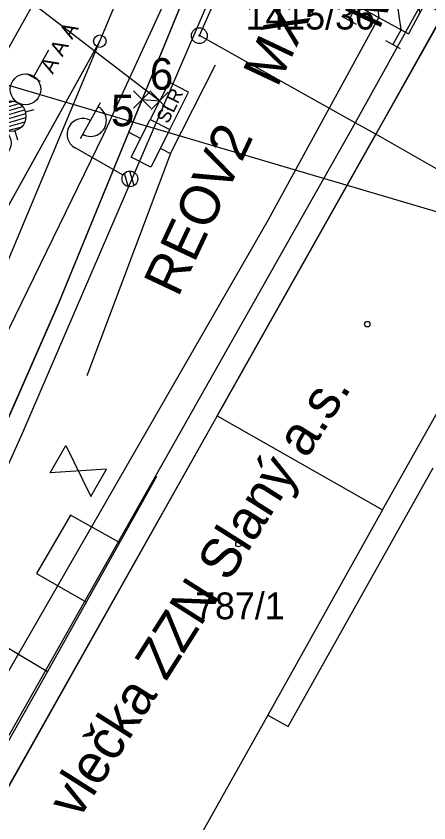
# Model space of a CAD drawing. Extents: x -781083 to -763634, y -1029516 to -1022695.
# Drawn here: x -764960.5 to -764934.3, y -1023880.9 to -1023829.7 of the extents above; entities that cross this region are included whole.
import ezdxf

# ---------------------------------------------------------------- set-up
doc = ezdxf.new("R2010")
doc.units = 0
for name, color, linetype in [('Default', 7, 'Continuous'), ('Hranice parcel', 7, 'Continuous'), ('Parcelní čísla', 7, 'Continuous'), ('PS110211-body_krizky', 7, 'Continuous'), ('PS110211-body_text', 7, 'Continuous'), ('PS120111-MOK', 7, 'Continuous'), ('PS_12-01-10_Kabelizace_nove_kabelizace', 7, 'Continuous'), ('PS_12-01-11_SZZ_Slany_nove_prvky', 7, 'Continuous'), ('PS_12-01-11_SZZ_Slany_rusene_prvky', 7, 'Continuous'), ('SO128401_EOV_popisky', 7, 'Continuous'), ('SO128401_EOV_prvky', 7, 'Continuous'), ('SO128401_EOV_trasa', 7, 'Continuous'), ('SO128602_NN_trasa', 7, 'Continuous'), ('Vnitřní kresba', 7, 'Continuous'), ('Vodafone_ vzduch', 7, 'Continuous'), ('Vrstva 1', 7, 'Continuous'), ('Vrstva 15', 7, 'Continuous'), ('Vrstva 17', 7, 'Continuous'), ('Vrstva 2', 7, 'Continuous'), ('Vrstva 21', 7, 'Continuous'), ('Vrstva 23', 7, 'Continuous'), ('Vrstva 25', 7, 'Continuous'), ('Vrstva 33', 7, 'Continuous'), ('Značky bodu BP', 7, 'Continuous'), ('Značky budov', 7, 'Continuous'), ('ČD Telematika_TK', 7, 'Continuous')]:
    doc.layers.add(name, color=color, linetype=linetype)

# ---------------------------------------------------------------- blocks, each defined once
blk = doc.blocks.new('4.02')
at = {"layer": 'Značky budov'}
blk.add_circle((-0.07, 0.01), 1.75, dxfattribs=at)
blk = doc.blocks.new('1.05')
at = {"layer": 'Značky bodu BP'}
for radius in [5, 0.303]:
    blk.add_circle((0, 0), radius, dxfattribs=at)
blk = doc.blocks.new('POINT_DISPLAY')
at = {"layer": 'Default'}
blk.add_line((0, 0), (0, 0), dxfattribs=at)
blk = doc.blocks.new('C689')
at = {"layer": 'Vrstva 15'}
for p, q in [((-10.66, 21.33), (-10.66, 10.66)), ((0, 21.33), (21.33, 21.34)), ((0, 16), (6.4, 21.33)), ((0, 21.33), (0, -21.33)), ((21.33, 21.34), (21.34, -21.33)), ((-10.66, 16), (0, 16)), ((21.33, 16), (0, 0)), ((0, -16), (21.33, 0)), ((-10.66, -10.66), (-10.66, -21.33)), ((0, -16), (-10.66, -16)), ((21.33, -16), (14.93, -21.33)), ((21.34, -21.33), (0, -21.33))]:
    blk.add_line(p, q, dxfattribs=at)
blk.add_blockref('POINT_DISPLAY', (0, 16), dxfattribs=at)
blk = doc.blocks.new('C687')
at = {"layer": 'Vrstva 21'}
blk.add_lwpolyline([(-10, -15), (10, -15), (-10, 15), (10, 15), (-10, -15)], dxfattribs=at)
blk = doc.blocks.new('C669_2')
at = {"layer": 'Vrstva 25'}
for p, q in [((0, 5), (0, 40)), ((6.99, 40), (33, 40)), ((-4.78, -1.46), (1.44, 4.76)), ((-2.39, -4.37), (4.38, 2.4))]:
    blk.add_line(p, q, dxfattribs=at)
blk.add_circle((0, 0), 5, dxfattribs=at)
blk.add_circle((0, 0), 5, dxfattribs=at)
for centre, start, end in [((10, 40), 359.9999, 179.9999), ((20, 39.88), 179.2973, 0.7025)]:
    blk.add_arc(centre, 10, start, end, dxfattribs=at)
blk = doc.blocks.new('C083_1')
at = {"layer": 'Vrstva 2'}
blk.add_circle((0, 0), 4, dxfattribs=at)
blk = doc.blocks.new('NS8')
at = {"layer": 'PS_12-01-11_SZZ_Slany_nove_prvky'}
for p, q in [((-10.61, 85.61), (-17, 92)), ((-14.92, 73.72), (1.27, 89.91)), ((-14.24, 79.71), (-4.75, 89.19)), ((-13.91, 69.42), (5.56, 88.89)), ((-11.99, 66.04), (8.96, 86.99)), ((10.61, 85.61), (17, 92)), ((-9.38, 63.35), (11.66, 84.39)), ((-6.1, 61.33), (13.69, 81.12)), ((-1.96, 60.16), (14.86, 76.98)), ((3.63, 60.45), (14.51, 71.33)), ((-10.61, 64.39), (-17, 58)), ((10.61, 64.39), (17, 58)), ((0, 30), (0, 0)), ((-15, 0), (15, 0))]:
    blk.add_line(p, q, dxfattribs=at)
for centre, radius in [((0, 105), 15), ((0, 75), 15), ((0, 45), 15), ((0, 45), 7)]:
    blk.add_circle(centre, radius, dxfattribs=at)
blk = doc.blocks.new('C016_3')
at = {"layer": 'PS_12-01-11_SZZ_Slany_rusene_prvky'}
for p, q in [((0, 5), (0, -5)), ((19.8, 0), (0, 0))]:
    blk.add_line(p, q, dxfattribs=at)

msp = doc.modelspace()

# ---------------------------------------------------------------- linework, layer by layer
at = {"layer": 'Hranice parcel'}
for points in [[(-764938.97, -1023836.45), (-764948.87, -1023830.92), (-764940.22, -1023811.42)], [(-764925.35, -1023824.17), (-764928.73, -1023830.14), (-764932.49, -1023827.93), (-764933.39, -1023829.54), (-764934.71, -1023828.79), (-764938.97, -1023836.45)], [(-764938.97, -1023836.45), (-764967.04, -1023886), (-764962.72, -1023888.96), (-764967.7, -1023897.5)], [(-764927.18, -1023843.13), (-764930.69, -1023841.15), (-764937.66, -1023837.18), (-764938.97, -1023836.45)]]:
    msp.add_lwpolyline(points, dxfattribs=at)
at = {"layer": 'PS110211-body_krizky'}
for p, q in [((-764953.054, -1023835.526), (-764951.954, -1023834.426)), ((-764951.954, -1023835.526), (-764953.054, -1023834.426)), ((-764953.054, -1023835.526), (-764951.954, -1023834.426)), ((-764951.954, -1023835.526), (-764953.054, -1023834.426)), ((-764951.943, -1023835.61), (-764950.843, -1023834.51)), ((-764950.843, -1023835.61), (-764951.943, -1023834.51)), ((-764951.943, -1023835.61), (-764950.843, -1023834.51)), ((-764950.843, -1023835.61), (-764951.943, -1023834.51)), ((-764952.504, -1023834.976), (-764952.504, -1023834.976)), ((-764952.504, -1023834.976), (-764952.504, -1023834.976)), ((-764951.393, -1023835.06), (-764951.393, -1023835.06)), ((-764951.393, -1023835.06), (-764951.393, -1023835.06))]:
    msp.add_line(p, q, dxfattribs=at)
at = {"layer": 'PS120111-MOK'}
msp.add_lwpolyline([(-764950.795, -1023833.874), (-764951.991, -1023836.246), (-764950.754, -1023836.87), (-764949.558, -1023834.498)], close=True, dxfattribs=at)
msp.add_lwpolyline([(-765225.805, -1024328.474), (-765227.041, -1024327.403), (-765189.607, -1024263.284), (-765167.089, -1024223.521), (-765111.836, -1024124.939), (-765108.851, -1024119.501), (-765085.73, -1024077.899), (-765081.023, -1024080.523), (-765060.822, -1024044.042), (-765057.835, -1024038.647), (-765021.888, -1023965.037), (-765009.529, -1023945.01), (-764990.029, -1023909.994), (-764973.93, -1023884.565), (-764957.796, -1023847.878), (-764953.349, -1023837.037), (-764952.504, -1023834.976), (-764951.393, -1023835.06)], dxfattribs=at)
at = {"layer": 'PS_12-01-10_Kabelizace_nove_kabelizace'}
msp.add_line((-764957.796, -1023847.878), (-764973.93, -1023884.565), dxfattribs=at)
msp.add_lwpolyline([(-764926.5, -1023779.725), (-764935.477, -1023793.468), (-764957.811, -1023847.911)], dxfattribs=at)
at = {"layer": 'SO128401_EOV_prvky'}
msp.add_lwpolyline([(-764950.754, -1023836.87), (-764951.962, -1023839.265), (-764953.199, -1023838.642), (-764951.991, -1023836.246)], close=True, dxfattribs=at)
at = {"layer": 'SO128401_EOV_trasa'}
for points in [[(-764953.349, -1023837.037), (-764935.477, -1023793.468), (-764926.5, -1023779.725), (-764918.394, -1023762.933), (-764916.418, -1023759.423), (-764914.161, -1023755.412), (-764908.579, -1023744.414)], [(-765060.824, -1024044.045), (-765057.835, -1024038.647), (-765021.888, -1023965.037), (-765009.529, -1023945.01), (-764990.029, -1023909.994), (-764973.93, -1023884.565), (-764973.93, -1023884.565), (-764957.796, -1023847.878), (-764957.796, -1023847.878), (-764953.349, -1023837.037), (-764953.349, -1023837.037), (-764952.595, -1023837.444), (-764952.595, -1023837.444), (-764952.595, -1023837.444), (-764952.595, -1023837.444)]]:
    msp.add_lwpolyline(points, dxfattribs=at)
at = {"layer": 'SO128602_NN_trasa'}
for points in [[(-764951.358, -1023838.068), (-764950.698, -1023838.4), (-764947.844, -1023832.776)], [(-764950.698, -1023838.4), (-764956.028, -1023852.51)]]:
    msp.add_lwpolyline(points, dxfattribs=at)
at = {"layer": 'Vnitřní kresba'}
for p, q in [((-764933.39, -1023829.54), (-764937.66, -1023837.18)), ((-764947.74, -1023855.04), (-764937.66, -1023837.18)), ((-764937.24, -1023861.02), (-764931.63, -1023851.06)), ((-764947.74, -1023855.04), (-764963.43, -1023882.91)), ((-764947.74, -1023855.04), (-764937.24, -1023861.02)), ((-764943.23, -1023874.77), (-764934.01, -1023858.35)), ((-764937.24, -1023861.02), (-764944.52, -1023874.04)), ((-764944.52, -1023874.04), (-764949.74, -1023883.33)), ((-764944.52, -1023874.04), (-764943.23, -1023874.77))]:
    msp.add_line(p, q, dxfattribs=at)
at = {"layer": 'Vodafone_ vzduch'}
msp.add_line((-764902.64, -1023851.29), (-765047.77, -1023808.471), dxfattribs=at)
at = {"layer": 'Vrstva 1'}
for points in [[(-765057.199, -1024002.967), (-765051.483, -1023992.806), (-765043.706, -1023978.953), (-765034.751, -1023962.958), (-765025.899, -1023947.163), (-765016.568, -1023930.575), (-765007.818, -1023915.05), (-764998.815, -1023899.045), (-764993.349, -1023889.308), (-764987.511, -1023878.918), (-764981.006, -1023867.343), (-764973.154, -1023853.353), (-764966.496, -1023841.495), (-764959.274, -1023828.66), (-764951.948, -1023815.612), (-764946.772, -1023806.407), (-764938.618, -1023791.934), (-764931.244, -1023778.835), (-764930.485, -1023777.473), (-764927.033, -1023771.438), (-764925.317, -1023768.417), (-764917.098, -1023753.973)], [(-765021.966, -1023959.899), (-765020.98, -1023958.139), (-765020.338, -1023956.998), (-765016.5, -1023950.137), (-765007.832, -1023934.643), (-765003.16, -1023926.347), (-764995.027, -1023911.884), (-764988.083, -1023899.535), (-764983.024, -1023890.503), (-764978.046, -1023881.533), (-764973.443, -1023872.721), (-764971.379, -1023868.593), (-764967.7, -1023860.663), (-764964.253, -1023852.828), (-764961.628, -1023846.609), (-764955.193, -1023831.268), (-764949.378, -1023817.406), (-764948.769, -1023815.942), (-764946.974, -1023811.649), (-764945.113, -1023807.171), (-764938.618, -1023791.934)], [(-764992.669, -1023917.221), (-764979.299, -1023898.88), (-764973.72, -1023891.071), (-764965.108, -1023878.355), (-764944.509, -1023842.632), (-764937.461, -1023829.77)], [(-765052.709, -1024004.781), (-765046.025, -1023992.89), (-765034.924, -1023973.118), (-765026.269, -1023957.734), (-765017.76, -1023942.588), (-765010.012, -1023928.764), (-765001.938, -1023914.334), (-764994.407, -1023900.905), (-764986.605, -1023887.067), (-764981.397, -1023877.846), (-764975.574, -1023867.554), (-764972.605, -1023862.288), (-764968.241, -1023854.565), (-764963.27, -1023845.769), (-764955.193, -1023831.268)]]:
    msp.add_lwpolyline(points, dxfattribs=at)
at = {"layer": 'Vrstva 17'}
for points in [[(-764965.992, -1023885.405), (-764965.453, -1023883.54), (-764958.526, -1023871.297), (-764951.567, -1023858.868)], [(-764958.526, -1023871.297), (-764962.765, -1023868.78)]]:
    msp.add_lwpolyline(points, dxfattribs=at)
at = {"layer": 'Vrstva 2'}
msp.add_line((-764963.27, -1023845.769), (-764955.193, -1023831.268), dxfattribs=at)
msp.add_lwpolyline([(-764961.628, -1023846.609), (-764955.193, -1023831.268), (-764949.378, -1023817.406), (-764948.769, -1023815.942)], dxfattribs=at)
at = {"layer": 'Vrstva 23'}
for points in [[(-764962.559, -1023881.396), (-764961.849, -1023880.039), (-764932.414, -1023827.868)], [(-764953.935, -1023863.082), (-764957.049, -1023861.343), (-764959.223, -1023865.06), (-764956.05, -1023866.88)]]:
    msp.add_lwpolyline(points, dxfattribs=at)
at = {"layer": 'Vrstva 33'}
msp.add_lwpolyline([(-764999.728, -1023799.281), (-764994.59, -1023801.95), (-764951.393, -1023835.06)], dxfattribs=at)
at = {"layer": 'ČD Telematika_TK'}
for points in [[(-764972.556, -1023882.882), (-764969.78, -1023867.575), (-764954.962, -1023837.207), (-764946.646, -1023819.145), (-764922.208, -1023770.145), (-764907.866, -1023743.998)], [(-765046.807, -1024017.08), (-765029.13, -1023984.48), (-765018.689, -1023963.431), (-765009.158, -1023943.676), (-764986.584, -1023911.367), (-764975.521, -1023895.82), (-764979.204, -1023891.861), (-764970.396, -1023879.031), (-764960.103, -1023856.143), (-764944.124, -1023819.068), (-764943.31, -1023819.61)]]:
    msp.add_lwpolyline(points, dxfattribs=at)

# ---------------------------------------------------------------- block references
at = {"layer": 'PS_12-01-11_SZZ_Slany_nove_prvky', "xscale": 0.065, "yscale": 0.06499999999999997, "rotation": -29.07790106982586}
msp.add_blockref('NS8', (-764963.233, -1023840.29), dxfattribs=at)
at = {"layer": 'PS_12-01-11_SZZ_Slany_rusene_prvky', "xscale": 0.1, "yscale": 0.10000000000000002, "rotation": 60.7065299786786}
msp.add_blockref('C016_3', (-764959.425, -1023833.569), dxfattribs=at)
at = {"layer": 'Vrstva 15', "xscale": 0.09999999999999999, "yscale": 0.09999999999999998, "rotation": 61.2784744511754}
msp.add_blockref('C689', (-764937.461, -1023829.77), dxfattribs=at)
at = {"layer": 'Vrstva 2', "xscale": 0.10000000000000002, "yscale": 0.1, "rotation": -112.7569505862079}
msp.add_blockref('C083_1', (-764955.193, -1023831.268), dxfattribs=at)
at = {"layer": 'Vrstva 21', "xscale": 0.10000000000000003, "yscale": 0.10000000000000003, "rotation": 60.030813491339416}
msp.add_blockref('C687', (-764956.561, -1023858.553), dxfattribs=at)
at = {"layer": 'Vrstva 25', "xscale": 0.09999999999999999, "yscale": 0.09999999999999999, "rotation": 60.56497035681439}
msp.add_blockref('C669_2', (-764953.286, -1023840.012), dxfattribs=at)
at = {"layer": 'Značky bodu BP', "xscale": 0.1, "yscale": 0.10000000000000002}
msp.add_blockref('1.05', (-764948.87, -1023830.92), dxfattribs=at)
at = {"layer": 'Značky budov', "xscale": 0.1, "yscale": 0.10000000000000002}
for p in [(-764938.19, -1023849.23), (-764946.38, -1023863.19)]:
    msp.add_blockref('4.02', p, dxfattribs=at)

# ---------------------------------------------------------------- texts
at = {"layer": 'Parcelní čísla'}
for s, p in [('1415/36', (-764945.939, -1023830.53)), ('787/1', (-764949.14, -1023867.96))]:
    msp.add_text(s, height=1.7, dxfattribs=at).set_placement(p)
at = {"layer": 'PS110211-body_text'}
for s, p in [('6', (-764952.021, -1023834.347)), ('5', (-764954.49, -1023836.666))]:
    msp.add_text(s, height=2, dxfattribs=at).set_placement(p)
at = {"layer": 'PS120111-MOK'}
msp.add_text('SLR', height=0.8629, rotation=63.2358, dxfattribs=at).set_placement((-764950.874, -1023836.558))
at = {"layer": 'PS_12-01-11_SZZ_Slany_rusene_prvky'}
msp.add_text('  A A A ', height=1, rotation=60.7065, dxfattribs=at).set_placement((-764958.553, -1023834.058))
at = {"layer": 'SO128401_EOV_popisky'}
for s, p in [('MX17.2', (-764937.468, -1023830.617)), ('MX17.1', (-764943.918, -1023834.272)), ('REOV2', (-764950.227, -1023847.582))]:
    msp.add_text(s, height=2.5, rotation=64.8129, dxfattribs=at).set_placement(p)
at = {"layer": 'Vrstva 1'}
msp.add_text('vlečka ZZN Slaný a.s.', height=2.5, rotation=57.6787, dxfattribs=at).set_placement((-764956.552, -1023880.735))

doc.saveas('drawing.dxf')
